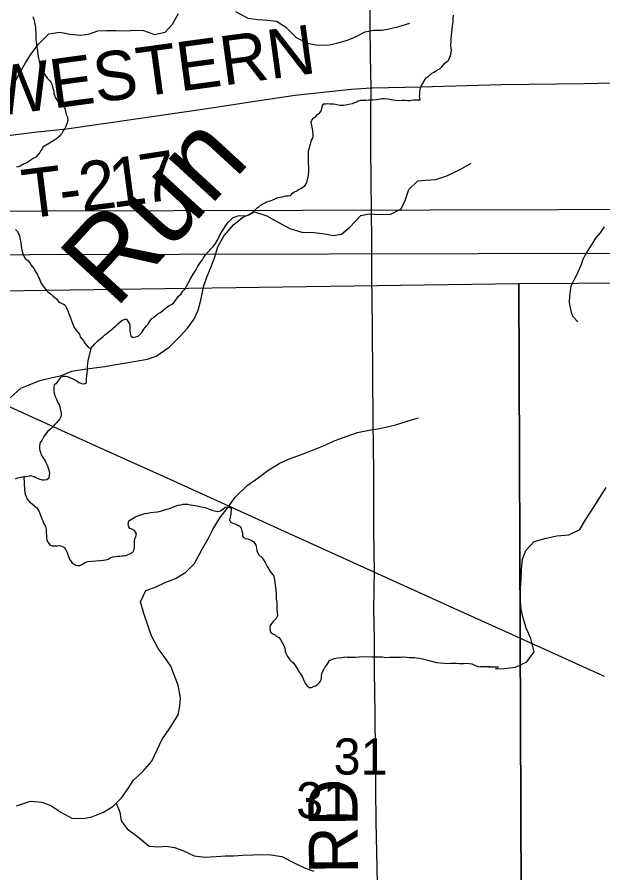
# Model space of a CAD drawing. Extents: x -21.1 to 50.3, y -4.9 to 22.1.
# Drawn here: x 2.902 to 3.578, y 19.251 to 20.24 of the extents above; entities that cross this region are included whole.
import ezdxf

# ---------------------------------------------------------------- set-up
doc = ezdxf.new("R2010")
doc.units = 0
for name, color, linetype in [('GM_X_Minor_River', 7, 'Continuous'), ('GM_X_Minor_River_Text', 7, 'Continuous'), ('GM_X_Section', 7, 'Continuous'), ('GM_X_Section_Text', 7, 'Continuous'), ('GM_X_Township_Road', 7, 'Continuous'), ('GM_X_Township_Road_Text', 7, 'Continuous'), ('GM_X_US_Route', 7, 'Continuous')]:
    doc.layers.add(name, color=color, linetype=linetype)

msp = doc.modelspace()

# ---------------------------------------------------------------- linework, layer by layer
at = {"layer": 'GM_X_Minor_River'}
for points in [[(2.89636, 20.15895), (2.90357, 20.17337), (2.91116, 20.18702), (2.91761, 20.19726), (2.92595, 20.20826), (2.93809, 20.2204), (2.95098, 20.2223), (2.96235, 20.22002), (2.97524, 20.21889), (2.9851, 20.2204), (2.99495, 20.22382), (3.00481, 20.2242), (3.01618, 20.2242), (3.02793, 20.22383), (3.03779, 20.22458), (3.04764, 20.22421), (3.06015, 20.21966), (3.07266, 20.22231), (3.081, 20.2318), (3.08821, 20.24394)], [(2.91991, 20.24035), (2.92101, 20.23691), (2.92173, 20.23386), (2.92208, 20.23195), (2.92244, 20.23004), (2.92279, 20.22814), (2.92275, 20.22509), (2.92307, 20.2209), (2.92303, 20.21824), (2.92338, 20.21596), (2.92335, 20.21368), (2.9237, 20.21139), (2.92405, 20.2091), (2.92441, 20.20719)], [(3.15379, 20.24622), (3.16819, 20.23863), (3.17956, 20.23712), (3.19094, 20.23636), (3.20117, 20.23522), (3.21178, 20.2284), (3.2239, 20.21626), (3.23679, 20.20982), (3.24702, 20.20792), (3.26067, 20.20755), (3.2709, 20.20983), (3.28342, 20.21324), (3.29327, 20.21741), (3.30389, 20.22272), (3.31337, 20.22462), (3.32322, 20.22462), (3.33308, 20.22652), (3.34256, 20.22879), (3.35545, 20.23297)], [(3.3672, 20.15545), (3.36761, 20.15811), (3.3684, 20.16), (3.37268, 20.16717), (3.37424, 20.16981), (3.37655, 20.1713), (3.38039, 20.17467), (3.38308, 20.17615), (3.38499, 20.17727), (3.3873, 20.17876), (3.38998, 20.18024), (3.39191, 20.18212), (3.39384, 20.18437), (3.39539, 20.18625), (3.3977, 20.18812), (3.39962, 20.18962), (3.40118, 20.19226), (3.40276, 20.1968), (3.40318, 20.19946), (3.40359, 20.20173), (3.40324, 20.2044), (3.40289, 20.20669), (3.40292, 20.20859), (3.40295, 20.21087), (3.40298, 20.21277), (3.40302, 20.21544), (3.40344, 20.21847), (3.40386, 20.22189), (3.40429, 20.22531), (3.40473, 20.22949), (3.40556, 20.23442), (3.40561, 20.23822), (3.40566, 20.24203)], [(2.92441, 20.20719), (2.92437, 20.20491), (2.92472, 20.20263), (2.92508, 20.20072), (2.92505, 20.19882), (2.92541, 20.19691), (2.92575, 20.19424), (2.9261, 20.19234), (2.92684, 20.19043), (2.92756, 20.18737), (2.92791, 20.18547), (2.92975, 20.18126), (2.93122, 20.17743), (2.93271, 20.17475), (2.93457, 20.17168), (2.93681, 20.16899), (2.93869, 20.16706), (2.94056, 20.16475), (2.94167, 20.16245), (2.94239, 20.1594), (2.94311, 20.15673), (2.94384, 20.15406), (2.94418, 20.15139), (2.94491, 20.14948), (2.94601, 20.14642), (2.94899, 20.14181), (2.952, 20.13911), (2.95463, 20.13679), (2.95688, 20.13448), (2.95759, 20.13067), (2.9583, 20.12723), (2.95978, 20.12417), (2.96011, 20.12036), (2.95931, 20.11771), (2.95852, 20.11582), (2.95773, 20.11355), (2.95656, 20.11128), (2.95462, 20.10865), (2.95344, 20.10562), (2.95151, 20.10374), (2.94997, 20.10186), (2.94689, 20.09924), (2.94458, 20.09775), (2.93499, 20.0918), (2.93308, 20.09069), (2.93116, 20.08957), (2.93037, 20.08768), (2.92883, 20.0858), (2.92765, 20.08353), (2.92533, 20.08052), (2.92301, 20.07789), (2.92071, 20.07678), (2.9188, 20.07567), (2.91534, 20.07343), (2.91342, 20.07194), (2.90883, 20.06972), (2.90499, 20.06749), (2.90079, 20.06641)], [(3.14331, 19.99993), (3.14564, 20.00332), (3.14911, 20.00631), (3.15141, 20.00818), (3.15485, 20.00928), (3.15677, 20.01039), (3.15868, 20.01075), (3.16324, 20.0103), (3.1659, 20.01026), (3.16857, 20.01099), (3.17125, 20.01209), (3.17472, 20.01547), (3.17702, 20.01734), (3.17896, 20.01959), (3.18088, 20.02071), (3.1828, 20.02258), (3.18778, 20.02518), (3.1897, 20.02629), (3.19275, 20.02701), (3.19504, 20.02774), (3.19696, 20.02886), (3.20002, 20.03033), (3.20308, 20.03143), (3.20575, 20.03178), (3.20804, 20.03213), (3.21033, 20.03286), (3.21262, 20.0332), (3.2149, 20.03317), (3.21756, 20.03352), (3.22027, 20.0369), (3.22219, 20.03802), (3.22487, 20.03912), (3.22679, 20.04061), (3.22947, 20.04172), (3.23216, 20.04358), (3.23407, 20.0447), (3.23602, 20.0481), (3.23681, 20.05037), (3.23723, 20.05264), (3.23802, 20.05492), (3.23844, 20.05795), (3.23849, 20.06137), (3.23852, 20.06404), (3.23856, 20.0667), (3.23823, 20.07013), (3.23843, 20.08496), (3.24164, 20.09747), (3.2432, 20.10011), (3.24362, 20.10276), (3.24365, 20.10504), (3.24332, 20.10847), (3.24261, 20.11267), (3.24227, 20.11495), (3.24155, 20.11839), (3.24196, 20.12066), (3.24428, 20.12329), (3.24659, 20.12516), (3.24891, 20.12779), (3.25082, 20.12891), (3.25237, 20.13079), (3.25316, 20.13306), (3.25396, 20.13571), (3.25437, 20.13761), (3.25591, 20.13949), (3.25782, 20.13946), (3.2601, 20.13981), (3.26276, 20.13977), (3.26505, 20.13974), (3.26733, 20.13971), (3.2696, 20.1393), (3.27453, 20.13809), (3.27948, 20.13802), (3.28482, 20.13909), (3.28901, 20.14017), (3.2936, 20.14201), (3.29552, 20.14313), (3.29819, 20.14385), (3.302, 20.1438), (3.30466, 20.14376), (3.30809, 20.14409), (3.31266, 20.14441), (3.31684, 20.14474), (3.31989, 20.14507), (3.32294, 20.14579), (3.32561, 20.14576), (3.32941, 20.14532), (3.33623, 20.14409), (3.34231, 20.14362), (3.3465, 20.14394), (3.34992, 20.1439), (3.35296, 20.14348), (3.35524, 20.14344), (3.35715, 20.1438), (3.35944, 20.14415), (3.36248, 20.14411), (3.36476, 20.14408), (3.36743, 20.14442), (3.36673, 20.14861), (3.36675, 20.15051), (3.36679, 20.15318), (3.3672, 20.15545)], [(3.06223, 19.84798), (3.0774, 19.8586), (3.08991, 19.87112), (3.09864, 19.8806), (3.10584, 19.89046), (3.11078, 19.90108), (3.1142, 19.91436), (3.11686, 19.92801), (3.12065, 19.93939), (3.12635, 19.95228), (3.12976, 19.96176), (3.13356, 19.97428), (3.14077, 19.98756), (3.15215, 20.00007), (3.16201, 20.00842), (3.17604, 20.01487), (3.19006, 20.01032), (3.20256, 20.00312), (3.21658, 19.99553), (3.23061, 19.99136), (3.24463, 19.99098), (3.25449, 19.98985), (3.267, 19.98757), (3.27647, 19.98909), (3.28595, 19.99706), (3.29885, 20.01071), (3.30833, 20.01261), (3.32159, 20.01185), (3.33335, 20.01223), (3.34548, 20.0183), (3.35003, 20.02779), (3.35421, 20.04068), (3.36445, 20.05054), (3.37393, 20.0513), (3.3853, 20.05206), (3.39819, 20.05662), (3.4126, 20.06344), (3.42625, 20.07103)], [(2.89981, 19.99453), (2.90168, 19.99261), (2.90354, 19.98915), (2.90427, 19.98724), (2.90462, 19.98458), (2.90533, 19.98114), (2.90568, 19.97886), (2.90639, 19.97542), (2.90674, 19.97276), (2.90745, 19.96932), (2.90853, 19.96512), (2.91076, 19.96091), (2.91377, 19.95859), (2.91639, 19.95589), (2.91788, 19.9532)], [(2.91788, 19.9532), (2.91937, 19.95128), (2.92124, 19.94897), (2.92198, 19.94706), (2.92309, 19.94515), (2.92459, 19.94322), (2.92607, 19.94016), (2.92755, 19.93748), (2.92901, 19.93289), (2.93274, 19.92752), (2.93611, 19.92328), (2.93912, 19.92096), (2.941, 19.91979), (2.94325, 19.91748), (2.94702, 19.91439), (2.94963, 19.91055), (2.9553, 19.90819), (2.95718, 19.90702), (2.95866, 19.90396), (2.96014, 19.90051), (2.96087, 19.89822), (2.96307, 19.89249), (2.96418, 19.89019), (2.96528, 19.88713), (2.96601, 19.88522), (2.96675, 19.8833), (2.96748, 19.88101), (2.96972, 19.87794), (2.97121, 19.87602), (2.97346, 19.87332), (2.97456, 19.87027), (2.9768, 19.86757), (2.9783, 19.86565), (2.97978, 19.86297), (2.98352, 19.85835), (2.98692, 19.85678), (2.98887, 19.8598), (2.99156, 19.86242), (2.99503, 19.8658), (2.99811, 19.86842), (3.0008, 19.87029), (3.00311, 19.87254), (3.00581, 19.87478), (3.0085, 19.87703), (3.01234, 19.88002), (3.01542, 19.88264), (3.01812, 19.88526), (3.02274, 19.88938), (3.02542, 19.89048), (3.02771, 19.89122), (3.0292, 19.88891), (3.0307, 19.88699), (3.0318, 19.88431), (3.03178, 19.88241), (3.03174, 19.87937), (3.0317, 19.87709), (3.03205, 19.8748), (3.03315, 19.87174), (3.03541, 19.86981), (3.03846, 19.87053), (3.04151, 19.87125), (3.04383, 19.8735), (3.04575, 19.87537), (3.04809, 19.87914), (3.05042, 19.88253), (3.05273, 19.88479), (3.05467, 19.8878), (3.057, 19.89119), (3.05969, 19.89306), (3.062, 19.89493), (3.06392, 19.89642), (3.06661, 19.89829), (3.06968, 19.90053), (3.07276, 19.90315), (3.07699, 19.90613), (3.08043, 19.90798), (3.08236, 19.90948), (3.08817, 19.91739), (3.09125, 19.92001), (3.09319, 19.92302), (3.09551, 19.92565), (3.09746, 19.92905), (3.0998, 19.9332), (3.10215, 19.93811), (3.10487, 19.94264), (3.1072, 19.94641), (3.10955, 19.95056), (3.11188, 19.95433), (3.11382, 19.95697), (3.11575, 19.95923), (3.11693, 19.96187), (3.11887, 19.96489), (3.12234, 19.96864), (3.12543, 19.97203), (3.12813, 19.97465), (3.13006, 19.97691), (3.13318, 19.98219), (3.13592, 19.98786), (3.13864, 19.99238), (3.14098, 19.99615), (3.14331, 19.99993)], [(3.57981, 19.99751), (3.57528, 19.99065), (3.56999, 19.98454), (3.5666, 19.97845), (3.56131, 19.97082), (3.55792, 19.9651), (3.55528, 19.95977), (3.55304, 19.95292), (3.54853, 19.94225), (3.54476, 19.93578), (3.54137, 19.92892), (3.54064, 19.9236), (3.53991, 19.91751), (3.53957, 19.91029), (3.54036, 19.90574), (3.54192, 19.89891), (3.54347, 19.89436), (3.5496, 19.88756)], [(2.98692, 19.85678), (2.98331, 19.84276), (2.98289, 19.83972), (2.98246, 19.83669), (2.98241, 19.8325), (2.98196, 19.82794), (2.98155, 19.82529), (2.9815, 19.82225), (2.98145, 19.81844), (2.98105, 19.81655), (2.97875, 19.81582), (2.97648, 19.81623), (2.97459, 19.81701), (2.97269, 19.81742), (2.97044, 19.81936), (2.96779, 19.82091), (2.96552, 19.8217), (2.96249, 19.82289), (2.96023, 19.82406), (2.95795, 19.82447), (2.95453, 19.82452), (2.95185, 19.82342), (2.94875, 19.81927), (2.94643, 19.81626), (2.94451, 19.81477), (2.94409, 19.81173), (2.94401, 19.80641), (2.94474, 19.80411), (2.94509, 19.80221), (2.94695, 19.79838), (2.94842, 19.79493), (2.94991, 19.79301), (2.95065, 19.7911), (2.95243, 19.78233), (2.9524, 19.78005), (2.95199, 19.77815), (2.95081, 19.7755), (2.94888, 19.77325), (2.94695, 19.77099), (2.94502, 19.76912), (2.94232, 19.76611), (2.94001, 19.76386), (2.93693, 19.76124), (2.93538, 19.75936), (2.93383, 19.75748), (2.93228, 19.75522), (2.93033, 19.75144), (2.92838, 19.74843), (2.92758, 19.74501), (2.92755, 19.74311), (2.92752, 19.74121), (2.92787, 19.73893), (2.92897, 19.73587), (2.92933, 19.73396), (2.93118, 19.73089), (2.93268, 19.72897), (2.93379, 19.72705), (2.93491, 19.72514), (2.93639, 19.72207), (2.93712, 19.72016), (2.93785, 19.71749), (2.93858, 19.71558), (2.93892, 19.71253), (2.93851, 19.71063), (2.93809, 19.70722), (2.93578, 19.70534), (2.93273, 19.70462), (2.93083, 19.70465), (2.92704, 19.70585), (2.92515, 19.70663), (2.92326, 19.70742), (2.92137, 19.70859), (2.91872, 19.70938), (2.91682, 19.70979), (2.91377, 19.70907), (2.91186, 19.70872), (2.9092, 19.70875), (2.90691, 19.7084), (2.90424, 19.70768), (2.90157, 19.70696), (2.89927, 19.70585)], [(2.8939, 19.80016), (2.90604, 19.81116), (2.91552, 19.81496), (2.92765, 19.81989), (2.94206, 19.82331), (2.95153, 19.8252), (2.9648, 19.8309), (2.97921, 19.83317), (2.99361, 19.83507), (3.00309, 19.83621), (3.01333, 19.83811), (3.02508, 19.84001), (3.05237, 19.84456), (3.06223, 19.84798)], [(3.22479, 19.7327), (3.23503, 19.73649), (3.24488, 19.74029), (3.25815, 19.7456), (3.26801, 19.75015), (3.2828, 19.75546), (3.29493, 19.76001), (3.3082, 19.76267), (3.32033, 19.76457), (3.33094, 19.76685), (3.34042, 19.76912), (3.35331, 19.7733), (3.36544, 19.77671)], [(2.90086, 19.32873), (2.91716, 19.33404), (2.93005, 19.33291), (2.94066, 19.32874), (2.95203, 19.32115), (2.96492, 19.31433), (2.97818, 19.31395), (2.98804, 19.31585), (3.00131, 19.32116), (3.01268, 19.32799), (3.02254, 19.33823), (3.02975, 19.34847), (3.0362, 19.35833), (3.04644, 19.36782), (3.05706, 19.38033), (3.06351, 19.39323), (3.06882, 19.40461), (3.07869, 19.4194), (3.08779, 19.43382), (3.08969, 19.44368), (3.09046, 19.45316), (3.08781, 19.46795), (3.08327, 19.47857), (3.0791, 19.48994), (3.07153, 19.50094), (3.06471, 19.51043), (3.05638, 19.52559), (3.05259, 19.53735), (3.04805, 19.55062), (3.04427, 19.56428), (3.05034, 19.57718), (3.06133, 19.58135), (3.07347, 19.58704), (3.08446, 19.59121), (3.0966, 19.59842), (3.10646, 19.60866), (3.11556, 19.62497), (3.12277, 19.63787), (3.1277, 19.64773), (3.13567, 19.66138), (3.14477, 19.67238), (3.1535, 19.68528), (3.16753, 19.69856), (3.17739, 19.70576), (3.19142, 19.71601), (3.20431, 19.72397), (3.21531, 19.7289), (3.22479, 19.7327)], [(2.9092, 19.70875), (2.91014, 19.6939), (2.91013, 19.69315), (2.91048, 19.69124), (2.91083, 19.68857), (2.91193, 19.68589), (2.91303, 19.68284), (2.91565, 19.68014), (2.91904, 19.67743), (2.92205, 19.67472), (2.92393, 19.67318), (2.92542, 19.67126), (2.92654, 19.66934), (2.92727, 19.66743), (2.93021, 19.66016), (2.93132, 19.65786), (2.93205, 19.65519), (2.93354, 19.65326), (2.93428, 19.65135), (2.935, 19.6483), (2.93532, 19.64449), (2.93567, 19.64183), (2.93562, 19.6384), (2.93596, 19.63536), (2.93745, 19.63267), (2.93931, 19.62998), (2.94195, 19.62881), (2.945, 19.62876), (2.94766, 19.62911), (2.95071, 19.62945), (2.95337, 19.62865), (2.95639, 19.62709), (2.95787, 19.6244), (2.95935, 19.62134), (2.96008, 19.61905), (2.96081, 19.61676), (2.96266, 19.61293), (2.96415, 19.61101), (2.96527, 19.60909), (2.96753, 19.60792), (2.96942, 19.60675), (2.9717, 19.60634), (2.9736, 19.60631), (2.97666, 19.60741), (2.97858, 19.6089), (2.98279, 19.61075), (2.99726, 19.61207), (3.00145, 19.61239), (3.00412, 19.61274), (3.00679, 19.61346), (3.00986, 19.61532), (3.01215, 19.61605), (3.01558, 19.61676), (3.01787, 19.61711), (3.02015, 19.61708), (3.02244, 19.61743), (3.02434, 19.6174), (3.02701, 19.61775), (3.0293, 19.61848), (3.03198, 19.61958), (3.03543, 19.62181), (3.03699, 19.62484), (3.03702, 19.62712), (3.03707, 19.63054), (3.03711, 19.63358), (3.03754, 19.637), (3.03872, 19.63965), (3.03952, 19.64268), (3.03729, 19.64651), (3.03427, 19.64808), (3.032, 19.64887), (3.0305, 19.65079), (3.02978, 19.65346), (3.03059, 19.65764), (3.03367, 19.65987), (3.0375, 19.6621), (3.04171, 19.66395), (3.04553, 19.66504), (3.04897, 19.66613), (3.0524, 19.66684), (3.05584, 19.66756), (3.05926, 19.66789), (3.06383, 19.66821), (3.06879, 19.66928), (3.07338, 19.67074), (3.07873, 19.67257), (3.08217, 19.67404), (3.08523, 19.67514), (3.08752, 19.67587), (3.09057, 19.67621), (3.09362, 19.67693), (3.09667, 19.67726), (3.09895, 19.67723), (3.10198, 19.67643), (3.10691, 19.6756), (3.10957, 19.67518), (3.11222, 19.67439), (3.1145, 19.67398), (3.1164, 19.67357), (3.11905, 19.67315), (3.12283, 19.67158)], [(3.45723, 19.48671), (3.45449, 19.48673), (3.46437, 19.48734), (3.47731, 19.48866), (3.4907, 19.49492), (3.49923, 19.50657), (3.49529, 19.52182), (3.48978, 19.53369), (3.48616, 19.5459), (3.48403, 19.55543), (3.48273, 19.56912), (3.48328, 19.58013), (3.48419, 19.58999), (3.48437, 19.60177), (3.48569, 19.61353), (3.48927, 19.62373), (3.49892, 19.63384), (3.51304, 19.63781), (3.52523, 19.64066), (3.53892, 19.64159), (3.55193, 19.64785), (3.55818, 19.65916), (3.56829, 19.6742), (3.57491, 19.68474), (3.58231, 19.6964)], [(3.12283, 19.67158), (3.12662, 19.67), (3.12965, 19.6692), (3.13269, 19.66878), (3.13459, 19.66913), (3.1365, 19.66949), (3.13957, 19.67173), (3.14226, 19.67359), (3.14531, 19.67393), (3.1472, 19.67353), (3.14909, 19.67236), (3.14861, 19.66514), (3.14781, 19.66211), (3.14701, 19.65907), (3.14811, 19.6564), (3.15189, 19.65482), (3.15454, 19.65403), (3.15681, 19.65247), (3.1587, 19.65169), (3.16057, 19.64938), (3.16128, 19.64633), (3.16201, 19.64365), (3.16197, 19.64099), (3.16271, 19.63908), (3.16535, 19.63752), (3.16801, 19.6371), (3.17028, 19.63631), (3.17292, 19.63513), (3.17518, 19.63358), (3.17741, 19.62975), (3.17813, 19.62669), (3.17847, 19.62365), (3.1792, 19.62136), (3.18106, 19.61867), (3.18482, 19.61519), (3.18631, 19.61289), (3.18817, 19.60982), (3.19039, 19.60523), (3.19411, 19.59947), (3.1971, 19.59562), (3.19822, 19.59371), (3.19857, 19.5918), (3.1996, 19.5838), (3.20032, 19.58036), (3.20067, 19.57846), (3.20065, 19.57656), (3.201, 19.57465), (3.20096, 19.57161), (3.2009, 19.56743), (3.20162, 19.56399), (3.20157, 19.56095), (3.20154, 19.55829), (3.20187, 19.55486), (3.20222, 19.55257), (3.20254, 19.54801), (3.20097, 19.54498), (3.1975, 19.54161), (3.19557, 19.53935), (3.19402, 19.53671), (3.19361, 19.53482), (3.19358, 19.53291), (3.19394, 19.53101), (3.19429, 19.5291), (3.19692, 19.52716), (3.19882, 19.52638), (3.2007, 19.52483), (3.20409, 19.52288), (3.20634, 19.52019), (3.20781, 19.51674), (3.20967, 19.51367), (3.21077, 19.51062), (3.21149, 19.50718), (3.21222, 19.50489), (3.21369, 19.50183), (3.21518, 19.49953), (3.21667, 19.49722), (3.21892, 19.49491), (3.22081, 19.49374), (3.22192, 19.49183), (3.22603, 19.48606), (3.22713, 19.48339), (3.22901, 19.48108), (3.23012, 19.47916), (3.23123, 19.47724), (3.2327, 19.47342), (3.23456, 19.47035), (3.23643, 19.46766), (3.23906, 19.46534), (3.24172, 19.46531), (3.24402, 19.46642), (3.24631, 19.46715), (3.24823, 19.46826), (3.25054, 19.47051), (3.25247, 19.47277), (3.25328, 19.47618), (3.25331, 19.47846), (3.25373, 19.4815), (3.25452, 19.48339), (3.25608, 19.48603), (3.25725, 19.48829), (3.25918, 19.49055)], [(3.25918, 19.49055), (3.26035, 19.49244), (3.26269, 19.49659), (3.26613, 19.49806), (3.26842, 19.49879), (3.27186, 19.49951), (3.27681, 19.49982), (3.28024, 19.50053), (3.2829, 19.50049), (3.29203, 19.50037), (3.2966, 19.50069), (3.30345, 19.50097), (3.31181, 19.50086), (3.31942, 19.50075), (3.3236, 19.50069), (3.32739, 19.49988), (3.33196, 19.5002), (3.33615, 19.50014), (3.34072, 19.50046), (3.34452, 19.50041), (3.34757, 19.50074), (3.35174, 19.50031), (3.35516, 19.49988), (3.35859, 19.49983), (3.36087, 19.4998), (3.36314, 19.49939), (3.36656, 19.49896), (3.36998, 19.49854), (3.37604, 19.49693), (3.38627, 19.49413), (3.39539, 19.49324), (3.40071, 19.49317), (3.40262, 19.49352), (3.40528, 19.49348), (3.40756, 19.49345), (3.40946, 19.49343), (3.4125, 19.493), (3.41478, 19.49297), (3.41745, 19.49294), (3.41973, 19.49329), (3.42391, 19.49285), (3.42695, 19.49243), (3.43187, 19.49046), (3.43452, 19.48966), (3.45798, 19.4888), (3.43718, 19.48962)], [(3.44571, 19.47495), (3.44574, 19.47493)], [(3.01613, 19.33157), (3.02026, 19.32116), (3.02177, 19.3113), (3.02859, 19.30182), (3.04072, 19.2931), (3.05398, 19.2821), (3.06383, 19.28134), (3.07407, 19.2821), (3.08354, 19.28059), (3.09302, 19.2768), (3.10628, 19.27073), (3.11841, 19.26922), (3.13168, 19.26998), (3.14191, 19.27074), (3.15215, 19.27074), (3.162, 19.2715), (3.17413, 19.27188), (3.18399, 19.27226), (3.1946, 19.27188), (3.20749, 19.26999), (3.22189, 19.26278), (3.2344, 19.25634), (3.24425, 19.25292)]]:
    msp.add_lwpolyline(points, dxfattribs=at)
at = {"layer": 'GM_X_Section'}
for points in [[(3.82397, 20.01814), (3.83539, 19.00471), (3.80166, 19.0044), (2.75941, 19.00342), (2.78495, 19.98), (2.78619, 20.01563)], [(3.78068, 19.96762), (3.7921, 18.95419), (3.75837, 18.95389), (2.71612, 18.9529), (2.74167, 19.92948), (2.74291, 19.96511)], [(3.4813, 19.9322), (4.49957, 19.93786), (4.50668, 19.00183), (4.50596, 18.94006), (3.48506, 18.92038)], [(3.4813, 19.9322), (3.48506, 18.92038), (2.48311, 18.9064), (2.47214, 19.91783)]]:
    msp.add_lwpolyline(points, close=True, dxfattribs=at)
at = {"layer": 'GM_X_Township_Road'}
for points in [[(3.31053, 20.15796), (3.3101, 20.19509), (3.3093, 20.26643), (3.30888, 20.35018), (3.30851, 20.37809), (3.30885, 20.40602), (3.30938, 20.41192), (3.30982, 20.41485)], [(3.31053, 20.15796), (3.31225, 20.1581), (3.36808, 20.15937), (3.46116, 20.16184), (3.55736, 20.16323), (3.65354, 20.1654), (3.66896, 20.16485), (3.678, 20.16344), (3.68378, 20.16161), (3.68927, 20.15905), (3.70508, 20.14918), (3.71363, 20.14516), (3.71965, 20.14333), (3.72896, 20.14181), (3.76933, 20.13983), (3.80968, 20.13887), (3.85, 20.13804), (3.85589, 20.13792)], [(2.81107, 20.03131), (2.8123, 20.03284), (2.81544, 20.03726), (2.82015, 20.04448), (2.8251, 20.0532), (2.8425, 20.08252), (2.84759, 20.09004), (2.85017, 20.09251), (2.85252, 20.09441), (2.85521, 20.0962), (2.85767, 20.09754), (2.8607, 20.09877), (2.86618, 20.10012), (2.87252, 20.10099), (2.89093, 20.10316), (2.9248, 20.10719), (2.95874, 20.11087), (3.03866, 20.12214), (3.1185, 20.1339), (3.18905, 20.14464), (3.22277, 20.14959), (3.28753, 20.1565), (3.31053, 20.15796)], [(3.31441, 19.5987), (3.31389, 19.6469), (3.31366, 19.7182), (3.31346, 19.73987), (3.31291, 19.77718), (3.31275, 19.82341), (3.31213, 19.88215), (3.31144, 19.94096), (3.3113, 19.98124), (3.31046, 20.08669), (3.31039, 20.13012), (3.31056, 20.1548), (3.31053, 20.15796)], [(3.32827, 18.6207), (3.32853, 18.6704), (3.32711, 18.72317), (3.32547, 18.79467), (3.32409, 18.86615), (3.32353, 18.89722), (3.32334, 18.92512), (3.32264, 18.97469), (3.32224, 18.99643), (3.32111, 19.06171), (3.32057, 19.09898), (3.31973, 19.15181), (3.3187, 19.19532), (3.31812, 19.23883), (3.31662, 19.31031), (3.31621, 19.34746), (3.31522, 19.43445), (3.31448, 19.48418), (3.31441, 19.52144), (3.31391, 19.5556), (3.31429, 19.57735), (3.31433, 19.5824), (3.31441, 19.5987)]]:
    msp.add_lwpolyline(points, dxfattribs=at)
at = {"layer": 'GM_X_US_Route'}
msp.add_lwpolyline([(2.81479, 19.82502), (2.84026, 19.81345), (2.91103, 19.78139), (3.0016, 19.74038), (3.07804, 19.70583), (3.13746, 19.67883), (3.20261, 19.64944), (3.31441, 19.5987), (3.39869, 19.56025), (3.46943, 19.52823), (3.57985, 19.47839)], dxfattribs=at)

# ---------------------------------------------------------------- texts
at = {"layer": 'GM_X_Minor_River_Text'}
msp.add_text('Run', height=0.094728, rotation=47.42794, dxfattribs=at).set_placement((3.01491, 19.90159))
at = {"layer": 'GM_X_Section_Text'}
for p in [(3.26735, 19.36463), (3.22406, 19.31411)]:
    msp.add_text('31', height=0.041856, rotation=0.00001, dxfattribs=at).set_placement(p)
at = {"layer": 'GM_X_Township_Road_Text'}
for s, height, rotation, p in [('WESTERN', 0.056818, 7.71151, (2.87219, 20.12441)), ('7', 0.05682, 8.70768, (3.0475, 20.02416)), ('2', 0.05682, 7.24136, (2.97651, 20.01493)), ('1', 0.05682, 7.5439, (3.01156, 20.01938)), ('T', 0.05682, 7.12608, (2.91106, 20.00674)), ('-', 0.05682, 7.15306, (2.95327, 20.01201)), ('RD', 0.056818, 90.49366, (3.29566, 19.25023))]:
    msp.add_text(s, height=height, rotation=rotation, dxfattribs=at).set_placement(p)

doc.saveas('drawing.dxf')
